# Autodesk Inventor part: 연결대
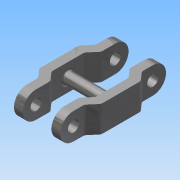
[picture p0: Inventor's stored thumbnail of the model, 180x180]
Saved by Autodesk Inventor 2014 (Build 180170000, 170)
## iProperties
Created: 2017-10
Part Number: 연결대
Material: 스테인리스강
Document SubType Name: Modeling
Designer: mduedu
Density: 8.08 g/cm^3
Mass: 37.9692 g
Surface Area: 35.7032 cm^2
Volume: 4.69916 cm^3
Appearance: 반광택
Author: mduedu
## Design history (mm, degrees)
sketch "스케치1"
  geometry: L1 (10, -7.497)-(10, 0); L2 (10, 0)-(14, 0); L3 (14, 0)-(14, -9); L4 (10.5, -24)-(6.5, -24); L5 (6.5, -24)-(6.5, -11.497); L6 (10.5, -13)-(10.5, -24); L7 (10.5, -13)-(14, -9); L8 (6.5, -11.497)-(10, -7.497); L9 (0, 0)-(10, 0); L10 (10, 7.497)-(10, 0); L11 (14, 0)-(14, 9); L12 (10.5, 24)-(6.5, 24); L13 (6.5, 24)-(6.5, 11.497); L14 (10.5, 13)-(10.5, 24); L15 (10.5, 13)-(14, 9); L16 (6.5, 11.497)-(10, 7.497)
  constraints: 32 end point, 6 symmetric about line, 4 parallel, 2 horizontal, 1 collinear, 1 horizontal alignment, 1 perpendicular, 1 vertical
  dimensions: "d0" = 10 distance from line of L1 L9.start; "d1" = 4 distance of L1.end L2.end; "d2" = 6.5 distance from line of L5 L9.start; "d4" = 24 distance between parallel lines of L4 L2; "d5" = 4 distance between parallel lines of L8 L7; "d6" = 9 distance of L2.end L3.end; "d7" = 11 distance of L6.start L4.start
extrude "돌출1" new body sketch "스케치1" distance "d8" = 12; taper "d9" = 0 deg
fillet "모깎기1"
fillet "모깎기2"
fillet "모깎기3" dims "d10" = 2, "d11" = 2
sketch "스케치2"
  geometry: L1 (-5.689, 12)-(-5.689, 0) reference; L2 (19.18, 0)-(19.18, 12) reference; L3 (-5.689, 6)-(19.18, 6); C1 r 2.5 at (6.746, 6); 1 further point
  constraints: 3 midpoint, 2 end point, 1 centre point, 1 vertical alignment
  dimensions: "d12" = 5 diameter of C1
extrude "돌출2" join sketch "스케치2" stored distance "d13" = 12; taper "d14" = 0 deg
fillet "모깎기4" dims "d15" = 1
sketch "스케치3"
  geometry: C1 r 2.5 at (0, 6); C2 r 2.5 at (36, 6); A1 r 6 centre (0, 6) between (0, 12) and (0, 0) reference; A2 r 6 centre (36, 6) between (36, 0) and (36, 12) reference; 1 further point
  constraints: 2 centre point, 2 coincident
  dimensions: "d16" = 5 diameter of C1; "d17" = 5 diameter of C2 (= d16)
extrude "돌출3" cut sketch "스케치3" stored distance "d18" = 12; taper "d19" = 0 deg
node "솔리드1"
mirror "대칭1"
